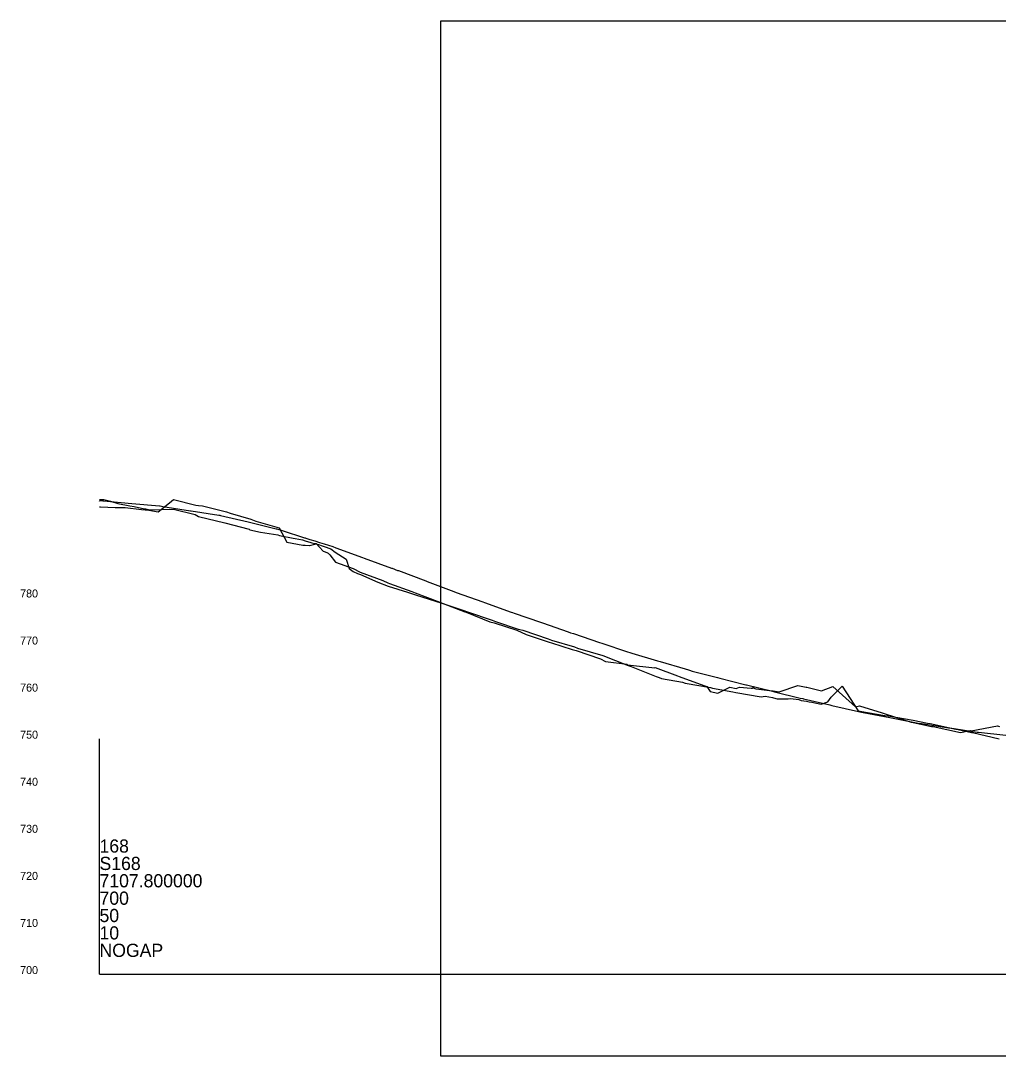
# Model space of a CAD drawing. Extents: x 1384070 to 1387149, y 1001217 to 1002317.
# Drawn here: x 1384070 to 1385108, y 1001217 to 1002317 of the extents above; entities that cross this region are included whole.
import ezdxf

# ---------------------------------------------------------------- set-up
doc = ezdxf.new("R2010")
doc.units = 0
for name, color, linetype in [('BR_EXIST_GROUND_LT', 7, 'Continuous'), ('BR_EXIST_GROUND_RT', 7, 'Continuous'), ('RD_DDB_ElevTX', 7, 'Continuous'), ('RD_DDB_Profile_EX', 7, 'Continuous'), ('RD_GPK_Profile_Cell', 7, 'Continuous'), ('RD_SHT_ShtClip', 7, 'Continuous')]:
    doc.layers.add(name, color=color, linetype=linetype)

msp = doc.modelspace()

# ---------------------------------------------------------------- linework, layer by layer
at = {"layer": 'BR_EXIST_GROUND_LT'}
msp.add_lwpolyline([(1384153.6, 1001808.5), (1384156.5, 1001808.3), (1384157.7, 1001808.2), (1384158.3, 1001808.2), (1384165.1, 1001806.7), (1384173.1, 1001804.1), (1384185.7, 1001801.7), (1384190.4, 1001800.9), (1384201.5, 1001798.5), (1384202.7, 1001798.4), (1384207.1, 1001797.4), (1384232.3, 1001798), (1384255.2, 1001792.3), (1384258.8, 1001790.4), (1384286.9, 1001783.5), (1384312.6, 1001776.8), (1384313.3, 1001776), (1384324.6, 1001773.6), (1384342.9, 1001770.7), (1384344.9, 1001770.3), (1384359.4, 1001767.3), (1384361.3, 1001767.1), (1384369.4, 1001765.7), (1384372, 1001764.5), (1384373, 1001764.1), (1384377.1, 1001762.9), (1384379.2, 1001762.3), (1384382.2, 1001761.8), (1384383.9, 1001761.5), (1384387.3, 1001757.7), (1384391.2, 1001753.5), (1384392.4, 1001753), (1384395.2, 1001751.9), (1384396.4, 1001751.5), (1384398.2, 1001749.6), (1384404.4, 1001741.8), (1384423, 1001735), (1384430.4, 1001731.2), (1384454.7, 1001722.4), (1384459.9, 1001719.9), (1384461.5, 1001719.3), (1384485.2, 1001710.6), (1384489, 1001709.1), (1384515.2, 1001699.4), (1384518.8, 1001698), (1384541.5, 1001689), (1384543.1, 1001688.6), (1384568.3, 1001678.6), (1384573, 1001677.3), (1384596.9, 1001669.4), (1384606.7, 1001665), (1384631.1, 1001656.9), (1384633.8, 1001656.1), (1384655.7, 1001649), (1384659.9, 1001647.8), (1384685.9, 1001639.3), (1384691.1, 1001636.3), (1384714.1, 1001633.3), (1384714.4, 1001632.6), (1384743.4, 1001629.7), (1384743.9, 1001629.8), (1384767.6, 1001621), (1384769.2, 1001620.5), (1384795.6, 1001610.8), (1384798.9, 1001609.9), (1384802.3, 1001604.3), (1384810.5, 1001602.8), (1384823.2, 1001608.9), (1384829.9, 1001607.6), (1384833.6, 1001609), (1384846, 1001607.9), (1384847, 1001607.9), (1384848.3, 1001609.1), (1384848.8, 1001607.9), (1384850.7, 1001607.4), (1384851.3, 1001607.3), (1384868, 1001605.2), (1384869.3, 1001605.2), (1384875.5, 1001604.1), (1384895.3, 1001610.9), (1384904.1, 1001609), (1384904.8, 1001608.9), (1384920.6, 1001605.2), (1384932.5, 1001609.6), (1384956.8, 1001588.1), (1384960.8, 1001589.3), (1384985.1, 1001581.6), (1384988.1, 1001580.8), (1385015.8, 1001572), (1385017.9, 1001571.4), (1385037.5, 1001567.3), (1385038, 1001567.3), (1385039.3, 1001567.2), (1385068.1, 1001561), (1385078.6, 1001563.1), (1385079.5, 1001562.8), (1385107.5, 1001567.8), (1385109.7, 1001567.2)], dxfattribs=at)
at = {"layer": 'BR_EXIST_GROUND_RT'}
msp.add_lwpolyline([(1384153.6, 1001800.5), (1384154.7, 1001800.5), (1384170.3, 1001800), (1384173, 1001800), (1384180.7, 1001800), (1384198.2, 1001797.6), (1384205.9, 1001797.2), (1384216, 1001795.2), (1384228.1, 1001805), (1384232.1, 1001808.2), (1384255.9, 1001802.4), (1384258.6, 1001802.1), (1384263, 1001801.6), (1384288.5, 1001795.4), (1384292.3, 1001793.8), (1384314.5, 1001787.5), (1384319.5, 1001785.3), (1384344.4, 1001778.2), (1384352.7, 1001763), (1384369.6, 1001759.9), (1384372, 1001759.7), (1384376.6, 1001759.5), (1384377.1, 1001759.6), (1384382.2, 1001761), (1384383.7, 1001761.4), (1384387.3, 1001760.1), (1384389.2, 1001759.5), (1384392.4, 1001758.4), (1384399.3, 1001755.9), (1384403.8, 1001752.3), (1384415.5, 1001745), (1384418.9, 1001735.1), (1384423.1, 1001732), (1384427.7, 1001729.9), (1384430.8, 1001728.8), (1384449.3, 1001720.5), (1384460.2, 1001716.2), (1384480.7, 1001709.8), (1384486.1, 1001708), (1384490.4, 1001706.6), (1384516.1, 1001698.5), (1384517.1, 1001698.1), (1384540.6, 1001690.4), (1384544.4, 1001688.9), (1384570.8, 1001680.2), (1384574.2, 1001678.9), (1384598.4, 1001670.7), (1384600.2, 1001670.3), (1384603.4, 1001669.5), (1384630.3, 1001660.3), (1384633.6, 1001659), (1384658.2, 1001651.7), (1384661.3, 1001650.5), (1384688.3, 1001642.5), (1384715.2, 1001632), (1384718.3, 1001630.9), (1384745, 1001620.5), (1384748.2, 1001619.3), (1384750.7, 1001618.3), (1384772.9, 1001614.3), (1384775.6, 1001613.2), (1384802.8, 1001608.5), (1384804.7, 1001608.1), (1384826.5, 1001604.2), (1384829.6, 1001603.4), (1384856.4, 1001598.7), (1384860.8, 1001599.3), (1384868.5, 1001598.2), (1384872, 1001597), (1384873.3, 1001596.7), (1384876.1, 1001596.5), (1384885.1, 1001596.8), (1384887.7, 1001596.9), (1384896.3, 1001595.9), (1384899, 1001595), (1384904.6, 1001594.2), (1384907.4, 1001593.5), (1384910.3, 1001593.1), (1384920.1, 1001590.9), (1384927.4, 1001593.3), (1384930.8, 1001598.4), (1384942.4, 1001610.1), (1384959.4, 1001583.9), (1384959.7, 1001583.9), (1384963.3, 1001583.3), (1384987.9, 1001579.1), (1384991.2, 1001578.6), (1385017.9, 1001574.1), (1385033.3, 1001570.8), (1385035.8, 1001570.3), (1385063.3, 1001564.4), (1385065.7, 1001564), (1385079.9, 1001560.8), (1385080.9, 1001560.7), (1385109.4, 1001554.3)], dxfattribs=at)
at = {"layer": 'RD_DDB_Profile_EX'}
msp.add_lwpolyline([(1384153.6, 1001806.6), (1384154.1, 1001807.2), (1384157.1, 1001807), (1384158, 1001807), (1384188, 1001804.2), (1384217.5, 1001801.6), (1384218, 1001801.5), (1384221, 1001801), (1384250.4, 1001796.5), (1384251, 1001796.4), (1384280.2, 1001791.9), (1384281, 1001791.8), (1384281.3, 1001791.7), (1384282, 1001791.5), (1384311.5, 1001784.5), (1384324.2, 1001781.4), (1384341.2, 1001777.3), (1384341.9, 1001777.1), (1384347.6, 1001775.3), (1384371.5, 1001767.8), (1384372, 1001767.6), (1384372.7, 1001767.4), (1384377.1, 1001766), (1384382.2, 1001764.4), (1384387.3, 1001762.8), (1384392.4, 1001761.2), (1384401.5, 1001758.4), (1384404.7, 1001757.2), (1384433.1, 1001746.8), (1384434.6, 1001746.2), (1384463.6, 1001735.6), (1384464.5, 1001735.3), (1384470.2, 1001733.1), (1384471.1, 1001732.8), (1384500.1, 1001721.9), (1384501.6, 1001721.3), (1384530, 1001710.6), (1384532.6, 1001709.7), (1384560.8, 1001699.6), (1384562.5, 1001699), (1384590.9, 1001688.8), (1384592.4, 1001688.3), (1384594.1, 1001687.7), (1384622.1, 1001678), (1384624.1, 1001677.3), (1384651.5, 1001667.8), (1384654, 1001666.9), (1384657.1, 1001665.9), (1384684.6, 1001656.6), (1384687.1, 1001655.8), (1384714.6, 1001646.5), (1384717, 1001645.7), (1384719.1, 1001645.1), (1384746.2, 1001637.1), (1384749.1, 1001636.2), (1384775.8, 1001628.4), (1384779.1, 1001627.4), (1384780.2, 1001627.1), (1384783.3, 1001626.2), (1384810.1, 1001619.3), (1384812.6, 1001618.7), (1384840.2, 1001611.6), (1384840.7, 1001611.4), (1384868.5, 1001604.7), (1384870.6, 1001604.2), (1384898, 1001597.5), (1384900.6, 1001596.9), (1384901.5, 1001596.7), (1384929.3, 1001590.2), (1384931.5, 1001589.7), (1384959.7, 1001583.1), (1384961.4, 1001582.7), (1384963.2, 1001582.4), (1384964.9, 1001582.1), (1384993.2, 1001576.7), (1384994.8, 1001576.3), (1385023.2, 1001570.9), (1385026.7, 1001570.4), (1385055.6, 1001566), (1385056.7, 1001565.8), (1385086, 1001561.3), (1385086.7, 1001561.2), (1385087.3, 1001561.2), (1385116.2, 1001558.2)], dxfattribs=at)
at = {"layer": 'RD_GPK_Profile_Cell'}
for q in [(1384153.6, 1001554.1), (1387149.1, 1001304.1), (1384153.6, 1001304.1)]:
    msp.add_line((1384153.6, 1001304.1), q, dxfattribs=at)
at = {"layer": 'RD_SHT_ShtClip'}
msp.add_lwpolyline([(1384516.2, 1002316.9), (1386316.2, 1002316.9), (1386316.2, 1001216.9), (1384516.2, 1001216.9)], close=True, dxfattribs=at)

# ---------------------------------------------------------------- texts
at = {"layer": 'RD_DDB_ElevTX'}
for s, p in [('780', (1384069.3, 1001704.3)), ('770', (1384069.3, 1001654.3)), ('760', (1384069.3, 1001604.3)), ('750', (1384069.3, 1001554.3)), ('740', (1384069.3, 1001504.3)), ('730', (1384069.3, 1001454.3)), ('720', (1384069.3, 1001404.3)), ('710', (1384069.3, 1001354.3)), ('700', (1384069.3, 1001304.3))]:
    msp.add_text(s, height=8.5, dxfattribs=at).set_placement(p)
at = {"layer": 'RD_GPK_Profile_Cell'}
for s, p in [('168', (1384153.6, 1001433.3)), ('S168', (1384153.6, 1001414.8)), ('7107.800000', (1384153.6, 1001396.4)), ('700', (1384153.6, 1001377.9)), ('50', (1384153.6, 1001359.5)), ('10', (1384153.6, 1001341)), ('NOGAP', (1384153.6, 1001322.5))]:
    msp.add_text(s, height=14, dxfattribs=at).set_placement(p)

doc.saveas('drawing.dxf')
